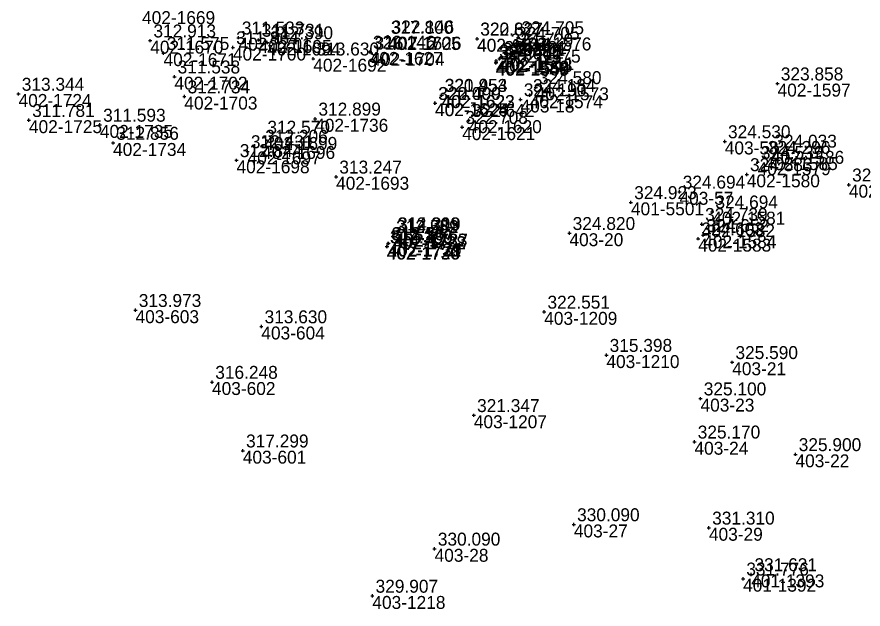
# Model space of a CAD drawing. Extents: x -829398 to -819400, y -1074439 to -1067977.
# Drawn here: x -824730.2 to -824651.7, y -1069844.4 to -1069789.5 of the extents above; entities that cross this region are included whole.
import ezdxf

# ---------------------------------------------------------------- set-up
doc = ezdxf.new("R2010")
doc.units = 0
for name, color, linetype in [('Vrstva 60', 7, 'Continuous'), ('Vrstva 61', 7, 'Continuous'), ('Čísla bodů_doměření_2012', 7, 'Continuous')]:
    doc.layers.add(name, color=color, linetype=linetype)

# ---------------------------------------------------------------- blocks, each defined once
blk = doc.blocks.new('BOD')
at = {"layer": 'Čísla bodů_doměření_2012'}
for p, q in [((-0.15, 0), (0.15, 0)), ((0, -0.15), (0, 0.15))]:
    blk.add_line(p, q, dxfattribs=at)

msp = doc.modelspace()

# ---------------------------------------------------------------- block references
at = {"layer": 'Vrstva 60'}
for p in [(-824717.83, -1069791.721), (-824709.633, -1069791.445), (-824707.783, -1069791.655), (-824706.972, -1069791.893), (-824695.811, -1069791.387), (-824695.742, -1069791.35), (-824687.514, -1069791.542), (-824687.504, -1069791.551), (-824683.688, -1069791.424), (-824710.156, -1069792.362), (-824684.683, -1069792.559), (-824684.1, -1069791.94), (-824716.596, -1069792.882), (-824702.703, -1069793.395), (-824697.471, -1069792.769), (-824697.316, -1069792.854), (-824685.44, -1069793.415), (-824685.281, -1069793.252), (-824685.777, -1069793.772), (-824685.747, -1069793.577), (-824685.733, -1069793.745), (-824715.587, -1069795.063), (-824659.633, -1069795.706), (-824682.065, -1069796.05), (-824730.047, -1069796.666), (-824714.666, -1069796.908), (-824690.817, -1069796.774), (-824690.788, -1069796.762), (-824683.47, -1069797.18), (-824682.623, -1069796.786), (-824691.415, -1069797.521), (-824691.397, -1069797.518), (-824702.529, -1069798.969), (-824729.083, -1069799.098), (-824722.501, -1069799.537), (-824688.892, -1069799.742), (-824688.286, -1069799.096), (-824721.277, -1069801.211), (-824707.261, -1069800.653), (-824664.53, -1069801.07), (-824708.794, -1069801.994), (-824707.459, -1069801.49), (-824660.232, -1069801.941), (-824709.824, -1069802.819), (-824660.833, -1069802.524), (-824661.482, -1069802.996), (-824700.588, -1069804.345), (-824662.488, -1069804.123), (-824653.016, -1069805.082), (-824668.73, -1069805.74), (-824673.234, -1069806.718), (-824665.696, -1069807.584), (-824666.654, -1069808.74), (-824695.327, -1069809.874), (-824695.306, -1069809.857), (-824695.193, -1069809.611), (-824695.135, -1069809.619), (-824678.94, -1069809.58), (-824666.525, -1069809.77), (-824695.753, -1069810.541), (-824695.723, -1069810.513), (-824666.999, -1069810.087), (-824695.895, -1069810.82), (-824695.855, -1069810.816), (-824719.193, -1069816.72), (-824681.279, -1069816.874), (-824707.523, -1069818.232), (-824675.511, -1069820.884), (-824663.84, -1069821.55), (-824712.099, -1069823.383), (-824666.78, -1069824.92), (-824687.809, -1069826.466), (-824667.34, -1069828.92), (-824709.24, -1069829.749), (-824657.97, -1069830.09), (-824678.53, -1069836.59), (-824666, -1069836.9), (-824691.45, -1069838.85), (-824662.075, -1069841.225), (-824662.83, -1069841.625), (-824697.224, -1069843.221)]:
    msp.add_blockref('BOD', p, dxfattribs=at)

# ---------------------------------------------------------------- texts
for s, p in [('402-1669', (-824718.589, -1069790.184)), ('402-1670', (-824717.83, -1069792.921)), ('402-1701', (-824709.633, -1069792.645)), ('402-1695', (-824707.783, -1069792.855)), ('402-1705', (-824695.811, -1069792.587)), ('402-1626', (-824695.742, -1069792.55)), ('402-1547', (-824687.514, -1069792.742)), ('402-1546', (-824687.504, -1069792.751)), ('402-1576', (-824683.688, -1069792.624)), ('402-1700', (-824710.156, -1069793.562)), ('402-1694', (-824706.972, -1069793.093)), ('402-1575', (-824684.683, -1069793.759)), ('403-17', (-824684.1, -1069793.14)), ('402-1671', (-824716.596, -1069794.082)), ('402-1627', (-824697.471, -1069793.969)), ('402-1704', (-824697.316, -1069794.054)), ('402-1551', (-824685.281, -1069794.452)), ('402-1692', (-824702.703, -1069794.595)), ('402-1549', (-824685.777, -1069794.972)), ('402-1552', (-824685.747, -1069794.777)), ('402-1550', (-824685.733, -1069794.945)), ('402-1548', (-824685.44, -1069794.615)), ('402-1702', (-824715.587, -1069796.263)), ('402-1597', (-824659.633, -1069796.906)), ('402-1573', (-824682.065, -1069797.25)), ('402-1724', (-824730.047, -1069797.866)), ('402-1703', (-824714.666, -1069798.108)), ('402-1622', (-824690.817, -1069797.974)), ('402-1623', (-824690.788, -1069797.962)), ('403-18', (-824683.47, -1069798.38)), ('402-1574', (-824682.623, -1069797.986)), ('402-1624', (-824691.415, -1069798.721)), ('402-1625', (-824691.397, -1069798.718)), ('402-1725', (-824729.083, -1069800.298)), ('402-1735', (-824722.501, -1069800.737)), ('402-1736', (-824702.529, -1069800.169)), ('402-1620', (-824688.286, -1069800.296)), ('402-1621', (-824688.892, -1069800.942)), ('402-1699', (-824707.261, -1069801.853)), ('403-58', (-824664.53, -1069802.27)), ('402-1734', (-824721.277, -1069802.411)), ('402-1696', (-824707.459, -1069802.69)), ('402-1586', (-824660.232, -1069803.141)), ('402-1697', (-824708.794, -1069803.194)), ('402-1585', (-824660.833, -1069803.724)), ('402-1698', (-824709.824, -1069804.019)), ('402-1579', (-824661.482, -1069804.196)), ('402-1580', (-824662.488, -1069805.323)), ('402-1693', (-824700.588, -1069805.545)), ('402-1644', (-824653.016, -1069806.282)), ('403-57', (-824668.73, -1069806.94)), ('401-5501', (-824673.234, -1069807.918)), ('402-1581', (-824665.696, -1069808.784)), ('402-1582', (-824666.654, -1069809.94)), ('402-1733', (-824695.193, -1069810.811)), ('402-1727', (-824695.135, -1069810.819)), ('403-20', (-824678.94, -1069810.78)), ('402-1584', (-824666.525, -1069810.97)), ('402-1731', (-824695.753, -1069811.741)), ('402-1729', (-824695.723, -1069811.713)), ('402-1732', (-824695.327, -1069811.074)), ('402-1728', (-824695.306, -1069811.057)), ('402-1583', (-824666.999, -1069811.287)), ('402-1730', (-824695.895, -1069812.02)), ('402-1726', (-824695.855, -1069812.016)), ('403-603', (-824719.193, -1069817.92)), ('403-1209', (-824681.279, -1069818.074)), ('403-604', (-824707.523, -1069819.432)), ('403-1210', (-824675.511, -1069822.084)), ('403-21', (-824663.84, -1069822.75)), ('403-602', (-824712.099, -1069824.583)), ('403-23', (-824666.78, -1069826.12)), ('403-1207', (-824687.809, -1069827.666)), ('403-24', (-824667.34, -1069830.12)), ('403-601', (-824709.24, -1069830.949)), ('403-22', (-824657.97, -1069831.29)), ('403-27', (-824678.53, -1069837.79)), ('403-29', (-824666, -1069838.1)), ('403-28', (-824691.45, -1069840.05)), ('401-1393', (-824662.075, -1069842.425)), ('401-1392', (-824662.83, -1069842.825)), ('403-1218', (-824697.224, -1069844.421))]:
    msp.add_text(s, height=1.2, dxfattribs=at).set_placement(p)
at = {"layer": 'Vrstva 61'}
for s, p in [('311.533', (-824709.333, -1069791.145)), ('311.731', (-824707.483, -1069791.355)), ('317.800', (-824695.511, -1069791.087)), ('322.146', (-824695.442, -1069791.05)), ('320.827', (-824687.214, -1069791.242)), ('322.627', (-824687.204, -1069791.251)), ('324.705', (-824683.388, -1069791.124)), ('312.913', (-824717.53, -1069791.421)), ('311.864', (-824709.856, -1069792.062)), ('312.390', (-824706.672, -1069791.593)), ('324.705', (-824683.8, -1069791.64)), ('311.575', (-824716.296, -1069792.582)), ('322.146', (-824697.171, -1069792.469)), ('316.712', (-824697.016, -1069792.554)), ('324.481', (-824684.981, -1069792.952)), ('324.729', (-824684.383, -1069792.259)), ('313.630', (-824702.403, -1069793.095)), ('324.060', (-824685.477, -1069793.472)), ('324.453', (-824685.447, -1069793.277)), ('324.441', (-824685.433, -1069793.445)), ('323.971', (-824685.14, -1069793.115)), ('311.538', (-824715.287, -1069794.763)), ('324.580', (-824681.765, -1069795.75)), ('323.858', (-824659.333, -1069795.406)), ('313.344', (-824729.747, -1069796.366)), ('312.734', (-824714.366, -1069796.608)), ('320.453', (-824690.517, -1069796.474)), ('321.954', (-824690.488, -1069796.462)), ('324.190', (-824683.17, -1069796.88)), ('324.184', (-824682.323, -1069796.486)), ('322.000', (-824691.115, -1069797.221)), ('320.499', (-824691.097, -1069797.218)), ('311.781', (-824728.783, -1069798.798)), ('311.593', (-824722.201, -1069799.237)), ('312.899', (-824702.229, -1069798.669)), ('322.642', (-824687.986, -1069798.796)), ('322.708', (-824688.592, -1069799.442)), ('312.570', (-824706.961, -1069800.353)), ('324.530', (-824664.23, -1069800.77)), ('312.856', (-824720.977, -1069800.911)), ('312.206', (-824707.159, -1069801.19)), ('312.431', (-824708.494, -1069801.694)), ('324.296', (-824660.533, -1069802.224)), ('324.033', (-824659.932, -1069801.641)), ('312.844', (-824709.524, -1069802.519)), ('324.539', (-824661.182, -1069802.696)), ('324.583', (-824662.188, -1069803.823)), ('313.247', (-824700.288, -1069804.045)), ('324.694', (-824668.43, -1069805.44)), ('324.492', (-824652.716, -1069804.782)), ('324.923', (-824672.934, -1069806.418)), ('324.694', (-824665.396, -1069807.284)), ('324.739', (-824666.354, -1069808.44)), ('312.393', (-824694.893, -1069809.311)), ('314.219', (-824694.835, -1069809.319)), ('324.820', (-824678.64, -1069809.28)), ('312.257', (-824695.453, -1069810.241)), ('313.587', (-824695.423, -1069810.213)), ('312.251', (-824695.027, -1069809.574)), ('313.589', (-824695.006, -1069809.557)), ('324.603', (-824666.699, -1069809.787)), ('324.652', (-824666.225, -1069809.47)), ('312.389', (-824695.595, -1069810.52)), ('314.180', (-824695.555, -1069810.516)), ('313.973', (-824718.893, -1069816.42)), ('322.551', (-824680.979, -1069816.574)), ('313.630', (-824707.223, -1069817.932)), ('315.398', (-824675.211, -1069820.584)), ('325.590', (-824663.54, -1069821.25)), ('316.248', (-824711.799, -1069823.083)), ('325.100', (-824666.48, -1069824.62)), ('321.347', (-824687.509, -1069826.166)), ('325.170', (-824667.04, -1069828.62)), ('317.299', (-824708.94, -1069829.449)), ('325.900', (-824657.67, -1069829.79)), ('330.090', (-824678.23, -1069836.29)), ('331.310', (-824665.7, -1069836.6)), ('330.090', (-824691.15, -1069838.55)), ('331.776', (-824662.53, -1069841.325)), ('331.631', (-824661.775, -1069840.925)), ('329.907', (-824696.924, -1069842.921))]:
    msp.add_text(s, height=1.2, dxfattribs=at).set_placement(p)

doc.saveas('drawing.dxf')
